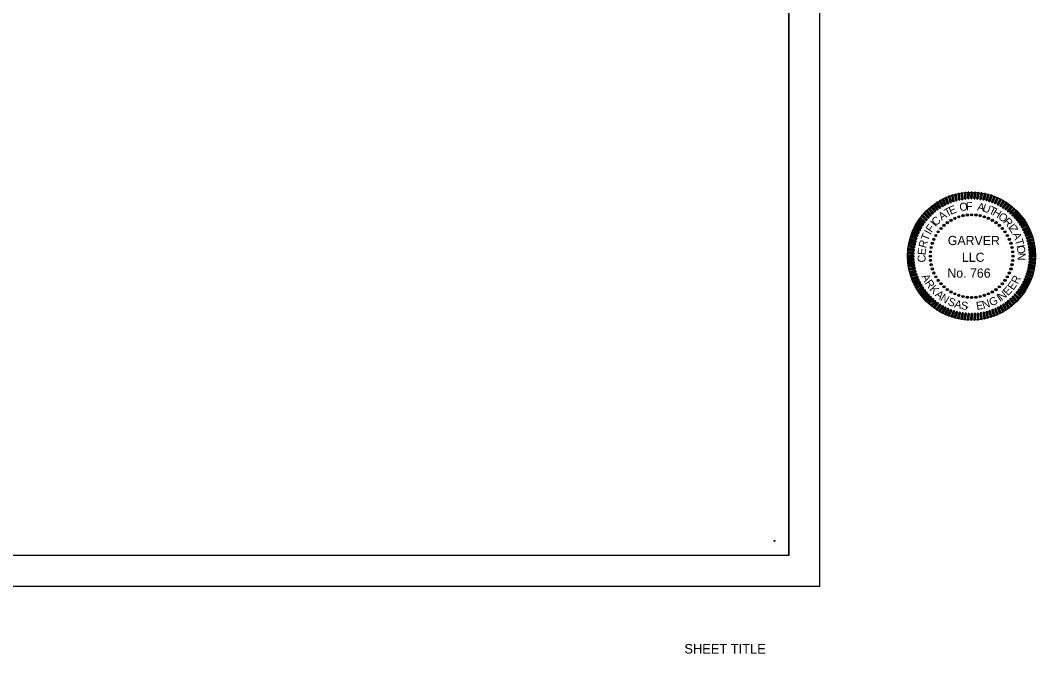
# Model space of a CAD drawing. Extents: x 0 to 38, y -1.3 to 22.5.
# Drawn here: x 19.02 to 38.05, y -1.27 to 10.6 of the extents above; entities that cross this region are included whole.
import ezdxf

# ---------------------------------------------------------------- set-up
doc = ezdxf.new("R2010")
doc.units = 0
for name, color, linetype in [('G-ANNO-STMP', 7, 'Continuous'), ('G-ANNO-TEXT', 7, 'Continuous'), ('G-Border-Paper', 7, 'Continuous'), ('G-Border-Sheet', 7, 'Continuous'), ('G-No Plot-Anchor', 7, 'Continuous'), ('G-No Plot-Border-1', 7, 'Continuous'), ('G-No Plot-Border-2', 7, 'Continuous'), ('G-No Plot-Stamp-1', 7, 'Continuous'), ('G-No Plot-Stamp-2', 7, 'Continuous')]:
    doc.layers.add(name, color=color, linetype=linetype)

# ---------------------------------------------------------------- blocks, each defined once
blk = doc.blocks.new('SEALDO')
at = {"layer": 'G-ANNO-TEXT'}
for radius in [0.0396, 0.0305, 0.0213, 0.0122, 0.00305]:
    blk.add_circle((1.403, -0.456), radius, dxfattribs=at)
blk = doc.blocks.new('SEALRI')
at = {"layer": 'G-ANNO-TEXT'}
for p, q in [((-0.023, 2.258), (-0.038, 2.081)), ((-0.008, 2.281), (-0.028, 2.056)), ((0.004, 2.286), (-0.016, 2.049)), ((0.016, 2.285), (-0.004, 2.048)), ((0.028, 2.278), (0.008, 2.052)), ((0.023, 2.076), (0.038, 2.253))]:
    blk.add_line(p, q, dxfattribs=at)
for centre, start, end in [((0.008, 2.256), 355, 175), ((-0.008, 2.078), 175, 355)]:
    blk.add_arc(centre, 0.0305, start, end, dxfattribs=at)

msp = doc.modelspace()

# ---------------------------------------------------------------- linework, layer by layer
at = {"layer": 'G-Border-Paper'}
msp.add_lwpolyline([(34, 22), (0, 22), (0, 0), (34, 0)], close=True, dxfattribs=at)
at = {"layer": 'G-Border-Sheet'}
for q in [(33.423, 21.423), (1.516, 0.577)]:
    msp.add_line((33.423, 0.577), q, dxfattribs=at)
at = {"layer": 'G-No Plot-Anchor'}
msp.add_circle((33.153, 0.847), 0.01, dxfattribs=at)
at = {"layer": 'G-No Plot-Border-1'}
msp.add_lwpolyline([(1.516, 0.577), (1.516, 21.423), (25.476, 21.423), (25.476, 20.432), (29.441, 20.432), (29.441, 20.122), (30.873, 20.122), (30.873, 17.172), (33.423, 17.172), (33.423, 0.577)], close=True, dxfattribs=at)
at = {"layer": 'G-No Plot-Border-2'}
msp.add_lwpolyline([(1.516, 0.577), (1.516, 21.423), (22.776, 21.423), (22.776, 18.473), (25.476, 18.473), (25.476, 20.432), (29.441, 20.432), (29.441, 20.122), (33.423, 20.122), (33.423, 0.577)], close=True, dxfattribs=at)
at = {"layer": 'G-No Plot-Stamp-1'}
msp.add_circle((36.844, 6.185), 1.2, dxfattribs=at)
at = {"layer": 'G-No Plot-Stamp-2'}
msp.add_circle((36.844, 6.185), 1.2, dxfattribs=at)

# ---------------------------------------------------------------- block references
at = {"layer": 'G-ANNO-STMP'}
for name, xscale, yscale, rotation in [('SEALRI', 0.524924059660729, 0.524924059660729, 30.00000000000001), ('SEALRI', 0.5249240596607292, 0.5249240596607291, 26.99999999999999), ('SEALRI', 0.5249240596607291, 0.5249240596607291, 23.99999999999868), ('SEALRI', 0.5249240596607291, 0.5249240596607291, 20.999999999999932), ('SEALRI', 0.524924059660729, 0.5249240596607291, 18), ('SEALRI', 0.524924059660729, 0.5249240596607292, 15.000000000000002), ('SEALRI', 0.524924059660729, 0.524924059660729, 12.000000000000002), ('SEALRI', 0.524924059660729, 0.524924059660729, 9), ('SEALRI', 0.5249240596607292, 0.5249240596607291, 6), ('SEALRI', 0.5249240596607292, 0.524924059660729, 3.0000000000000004), ('SEALRI', 0.5249240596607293, 0.5249240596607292, -2.9999999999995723), ('SEALRI', 0.524924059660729, 0.524924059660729, -5.9999999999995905), ('SEALRI', 0.5249240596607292, 0.5249240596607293, -8.999999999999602), ('SEALRI', 0.524924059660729, 0.5249240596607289, -11.999999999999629), ('SEALRI', 0.524924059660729, 0.524924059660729, -14.999999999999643), ('SEALRI', 0.5249240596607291, 0.524924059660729, -17.99999999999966), ('SEALRI', 0.524924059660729, 0.5249240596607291, -20.999999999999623), ('SEALRI', 0.524924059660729, 0.5249240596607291, -23.999999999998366), ('SEALRI', 0.5249240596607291, 0.5249240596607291, -26.999999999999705), ('SEALRI', 0.5249240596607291, 0.524924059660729, -29.99999999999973), ('SEALRI', 0.5249240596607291, 0.524924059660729, 44.999999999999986), ('SEALRI', 0.5249240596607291, 0.5249240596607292, 41.999999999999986), ('SEALRI', 0.5249240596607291, 0.5249240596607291, 38.999999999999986), ('SEALRI', 0.524924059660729, 0.524924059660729, 36), ('SEALRI', 0.524924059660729, 0.5249240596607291, 33), ('SEALRI', 0.5249240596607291, 0.524924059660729, -32.999999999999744), ('SEALRI', 0.524924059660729, 0.524924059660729, -35.999999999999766), ('SEALRI', 0.5249240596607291, 0.524924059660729, -38.999999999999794), ('SEALRI', 0.5249240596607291, 0.524924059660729, -41.99999999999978), ('SEALRI', 0.5249240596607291, 0.5249240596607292, -44.999999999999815), ('SEALRI', 0.5249240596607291, 0.524924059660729, 56.99999999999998), ('SEALRI', 0.524924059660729, 0.524924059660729, 54), ('SEALRI', 0.5249240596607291, 0.5249240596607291, 50.99999999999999), ('SEALRI', 0.5249240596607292, 0.5249240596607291, 47.99999999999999), ('SEALDO', 0.5249240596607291, 0.5249240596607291, 138), ('SEALDO', 0.524924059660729, 0.5249240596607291, 131.99999999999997), ('SEALDO', 0.5249240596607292, 0.5249240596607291, 125.99999999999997), ('SEALDO', 0.524924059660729, 0.5249240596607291, 119.99999999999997), ('SEALDO', 0.524924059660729, 0.5249240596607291, 113.99999999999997), ('SEALDO', 0.5249240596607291, 0.5249240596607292, 107.99999999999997), ('SEALDO', 0.5249240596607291, 0.5249240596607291, 101.99999999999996), ('SEALDO', 0.5249240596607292, 0.524924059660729, 95.99999999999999), ('SEALDO', 0.5249240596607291, 0.5249240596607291, 90), ('SEALDO', 0.5249240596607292, 0.5249240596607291, 83.99999999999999), ('SEALDO', 0.524924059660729, 0.5249240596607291, 77.99999999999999), ('SEALRI', 0.5249240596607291, 0.5249240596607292, -47.99999999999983), ('SEALRI', 0.524924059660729, 0.5249240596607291, -50.999999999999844), ('SEALRI', 0.524924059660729, 0.5249240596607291, -53.99999999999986), ('SEALRI', 0.5249240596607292, 0.5249240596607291, -56.999999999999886), ('SEALRI', 0.5249240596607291, 0.5249240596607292, 65.99999999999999), ('SEALRI', 0.5249240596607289, 0.524924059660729, 63), ('SEALRI', 0.524924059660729, 0.524924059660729, 59.999999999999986), ('SEALDO', 0.524924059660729, 0.5249240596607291, 162.00000000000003), ('SEALDO', 0.5249240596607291, 0.5249240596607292, 156.00000000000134), ('SEALDO', 0.5249240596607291, 0.524924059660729, 150), ('SEALDO', 0.524924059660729, 0.5249240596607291, 144), ('SEALDO', 0.524924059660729, 0.5249240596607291, 72), ('SEALDO', 0.5249240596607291, 0.5249240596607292, 66.00000000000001), ('SEALDO', 0.5249240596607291, 0.524924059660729, 60.00000000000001), ('SEALDO', 0.524924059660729, 0.524924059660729, 54), ('SEALRI', 0.524924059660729, 0.5249240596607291, -59.99999999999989), ('SEALRI', 0.5249240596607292, 0.5249240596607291, -62.99999999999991), ('SEALRI', 0.5249240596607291, 0.5249240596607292, -65.99999999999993), ('SEALRI', 0.524924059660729, 0.5249240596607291, 75.00000000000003), ('SEALRI', 0.524924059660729, 0.5249240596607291, 72), ('SEALRI', 0.5249240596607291, 0.5249240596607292, 68.99999999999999), ('SEALDO', 0.5249240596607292, 0.524924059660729, 174.00000000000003), ('SEALDO', 0.5249240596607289, 0.524924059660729, 168.00000000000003), ('SEALDO', 0.5249240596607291, 0.5249240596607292, 48.00000000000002), ('SEALDO', 0.5249240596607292, 0.5249240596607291, 42.000000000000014), ('SEALRI', 0.5249240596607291, 0.5249240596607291, -68.99999999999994), ('SEALRI', 0.5249240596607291, 0.5249240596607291, -71.99999999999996), ('SEALRI', 0.5249240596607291, 0.5249240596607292, -74.99999999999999), ('SEALRI', 0.5249240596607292, 0.5249240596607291, 84.00000000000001), ('SEALRI', 0.524924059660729, 0.524924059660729, 81), ('SEALRI', 0.524924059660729, 0.524924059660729, 78.00000000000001), ('SEALDO', 0.524924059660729, 0.5249240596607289, -167.99999999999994), ('SEALDO', 0.5249240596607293, 0.5249240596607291, -173.99999999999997), ('SEALDO', 0.5249240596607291, 0.5249240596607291, -179.99999999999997), ('SEALDO', 0.524924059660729, 0.524924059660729, 36), ('SEALDO', 0.5249240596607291, 0.524924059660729, 29.999999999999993), ('SEALDO', 0.5249240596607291, 0.5249240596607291, 23.99999999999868), ('SEALRI', 0.524924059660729, 0.524924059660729, -78), ('SEALRI', 0.524924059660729, 0.524924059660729, -81.00000000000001), ('SEALRI', 0.5249240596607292, 0.524924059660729, -84.00000000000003), ('SEALRI', 0.5249240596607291, 0.5249240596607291, 90.00000000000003), ('SEALRI', 0.5249240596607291, 0.5249240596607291, 87.00000000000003), ('SEALRI', 0.5249240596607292, 0.524924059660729, 93), ('SEALRI', 0.5249240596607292, 0.5249240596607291, 96.00000000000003), ('SEALDO', 0.524924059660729, 0.5249240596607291, -161.99999999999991), ('SEALDO', 0.524924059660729, 0.5249240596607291, -156.00000000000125), ('SEALDO', 0.524924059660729, 0.524924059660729, 12.000000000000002), ('SEALDO', 0.524924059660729, 0.5249240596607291, 18), ('SEALRI', 0.5249240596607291, 0.524924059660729, -96.0000000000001), ('SEALRI', 0.5249240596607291, 0.5249240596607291, -87.00000000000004), ('SEALRI', 0.5249240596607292, 0.5249240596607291, -93.00000000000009), ('SEALRI', 0.5249240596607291, 0.5249240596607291, -90.00000000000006), ('SEALRI', 0.5249240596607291, 0.5249240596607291, 99.00000000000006), ('SEALRI', 0.524924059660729, 0.5249240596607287, 102.00000000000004), ('SEALRI', 0.5249240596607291, 0.5249240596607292, 105.00000000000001), ('SEALDO', 0.5249240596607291, 0.5249240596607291, -149.99999999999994), ('SEALDO', 0.5249240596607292, 0.5249240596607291, -143.99999999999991), ('SEALDO', 0.5249240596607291, 0.5249240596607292, -137.9999999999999), ('SEALDO', 0.5249240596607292, 0.5249240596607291, 6), ('SEALRI', 0.5249240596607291, 0.524924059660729, -105.00000000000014), ('SEALRI', 0.524924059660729, 0.524924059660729, -102.00000000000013), ('SEALRI', 0.5249240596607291, 0.524924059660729, -99.00000000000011), ('SEALRI', 0.5249240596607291, 0.5249240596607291, 108.00000000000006), ('SEALRI', 0.524924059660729, 0.524924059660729, 111.00000000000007), ('SEALRI', 0.5249240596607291, 0.5249240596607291, 114.00000000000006), ('SEALRI', 0.5249240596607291, 0.5249240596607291, 117.00000000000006), ('SEALDO', 0.5249240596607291, 0.5249240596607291, -131.99999999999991), ('SEALDO', 0.5249240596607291, 0.5249240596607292, -125.9999999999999), ('SEALDO', 0.524924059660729, 0.5249240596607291, -18.000000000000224), ('SEALDO', 0.524924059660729, 0.5249240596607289, -12.000000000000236), ('SEALDO', 0.5249240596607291, 0.524924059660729, -6.000000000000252), ('SEALRI', 0.5249240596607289, 0.524924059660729, -117.00000000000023), ('SEALRI', 0.5249240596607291, 0.5249240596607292, -114.0000000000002), ('SEALRI', 0.5249240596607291, 0.5249240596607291, -111.00000000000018), ('SEALRI', 0.5249240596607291, 0.524924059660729, -108.00000000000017), ('SEALRI', 0.524924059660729, 0.524924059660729, 120.00000000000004), ('SEALRI', 0.524924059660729, 0.524924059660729, 123.00000000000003), ('SEALRI', 0.5249240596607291, 0.5249240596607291, 126.00000000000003), ('SEALRI', 0.5249240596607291, 0.5249240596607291, 129.00000000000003), ('SEALDO', 0.524924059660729, 0.5249240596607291, -119.99999999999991), ('SEALDO', 0.5249240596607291, 0.5249240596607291, -113.99999999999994), ('SEALDO', 0.5249240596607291, 0.5249240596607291, -107.99999999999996), ('SEALDO', 0.524924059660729, 0.5249240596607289, -101.99999999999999), ('SEALDO', 0.524924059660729, 0.524924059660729, -42.00000000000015), ('SEALDO', 0.524924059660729, 0.5249240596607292, -36.00000000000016), ('SEALDO', 0.524924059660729, 0.5249240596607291, -30.00000000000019), ('SEALDO', 0.5249240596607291, 0.524924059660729, -23.999999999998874), ('SEALRI', 0.524924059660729, 0.5249240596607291, -129.00000000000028), ('SEALRI', 0.5249240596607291, 0.524924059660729, -126.00000000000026), ('SEALRI', 0.524924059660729, 0.5249240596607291, -123.00000000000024), ('SEALRI', 0.5249240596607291, 0.524924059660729, -120.00000000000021), ('SEALRI', 0.5249240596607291, 0.524924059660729, 132), ('SEALRI', 0.524924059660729, 0.5249240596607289, 135), ('SEALRI', 0.5249240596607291, 0.5249240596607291, 138), ('SEALRI', 0.524924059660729, 0.5249240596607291, 140.99999999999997), ('SEALRI', 0.524924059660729, 0.5249240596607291, 144), ('SEALDO', 0.5249240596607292, 0.5249240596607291, -96), ('SEALDO', 0.5249240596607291, 0.5249240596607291, -90.00000000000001), ('SEALDO', 0.5249240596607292, 0.524924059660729, -84.00000000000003), ('SEALDO', 0.5249240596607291, 0.5249240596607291, -78.00000000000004), ('SEALDO', 0.5249240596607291, 0.524924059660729, -72.00000000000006), ('SEALDO', 0.524924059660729, 0.5249240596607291, -66.00000000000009), ('SEALDO', 0.5249240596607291, 0.5249240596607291, -60.0000000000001), ('SEALDO', 0.5249240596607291, 0.5249240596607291, -54.000000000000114), ('SEALDO', 0.5249240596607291, 0.5249240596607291, -48.00000000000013), ('SEALRI', 0.524924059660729, 0.5249240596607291, -144.00000000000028), ('SEALRI', 0.5249240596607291, 0.524924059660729, -141.0000000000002), ('SEALRI', 0.5249240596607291, 0.524924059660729, -138.00000000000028), ('SEALRI', 0.524924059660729, 0.524924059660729, -135.00000000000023), ('SEALRI', 0.524924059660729, 0.5249240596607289, -132.00000000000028), ('SEALRI', 0.524924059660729, 0.5249240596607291, 146.99999999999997), ('SEALRI', 0.524924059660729, 0.5249240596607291, 149.99999999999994), ('SEALRI', 0.5249240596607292, 0.5249240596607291, 152.99999999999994), ('SEALRI', 0.524924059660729, 0.524924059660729, 156.00000000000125), ('SEALRI', 0.524924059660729, 0.5249240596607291, 159), ('SEALRI', 0.524924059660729, 0.524924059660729, 161.99999999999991), ('SEALRI', 0.524924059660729, 0.5249240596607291, 164.99999999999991), ('SEALRI', 0.524924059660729, 0.5249240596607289, 167.99999999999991), ('SEALRI', 0.524924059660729, 0.524924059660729, -168.0000000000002), ('SEALRI', 0.524924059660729, 0.5249240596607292, -165.0000000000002), ('SEALRI', 0.524924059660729, 0.5249240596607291, -162.00000000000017), ('SEALRI', 0.5249240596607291, 0.5249240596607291, -159.00000000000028), ('SEALRI', 0.5249240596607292, 0.5249240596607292, -156.00000000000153), ('SEALRI', 0.524924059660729, 0.5249240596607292, -153.00000000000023), ('SEALRI', 0.524924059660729, 0.5249240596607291, -150.00000000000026), ('SEALRI', 0.5249240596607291, 0.524924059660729, -147.00000000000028), ('SEALRI', 0.5249240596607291, 0.524924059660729, 170.9999999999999), ('SEALRI', 0.5249240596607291, 0.524924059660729, 173.9999999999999), ('SEALRI', 0.5249240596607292, 0.5249240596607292, 176.9999999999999), ('SEALRI', 0.5249240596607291, 0.5249240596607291, 179.99999999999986), ('SEALRI', 0.5249240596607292, 0.5249240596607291, -177.00000000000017), ('SEALRI', 0.524924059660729, 0.524924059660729, -174.00000000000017), ('SEALRI', 0.5249240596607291, 0.5249240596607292, -171.00000000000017)]:
    msp.add_blockref(name, (36.845, 6.185), dxfattribs=dict(at, xscale=xscale, yscale=yscale, rotation=rotation))
at = {"layer": 'G-ANNO-STMP', "xscale": 0.5249240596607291, "yscale": 0.5249240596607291}
for name in ['SEALRI', 'SEALDO']:
    msp.add_blockref(name, (36.845, 6.185), dxfattribs=at)

# ---------------------------------------------------------------- texts
at = {"layer": 'G-ANNO-STMP'}
for s, rotation, p in [('T', 28.2771, (36.381, 6.915)), ('E', 21.6104, (36.453, 6.957)), ('O', 8.2771, (36.627, 7.025)), ('F', 1.6104, (36.741, 7.044)), ('A', 348.2771, (36.941, 7.045)), ('U', 341.2772, (37.035, 7.03)), ('T', 334.9438, (37.153, 6.992)), ('H', 328.2771, (37.221, 6.966)), ('I', 49.7408, (36.172, 6.724)), ('C', 44.3881, (36.179, 6.74)), ('A', 34.9438, (36.286, 6.846)), ('O', 319.7874, (37.329, 6.904)), ('R', 311.9933, (37.427, 6.826)), ('I', 61.6104, (36.076, 6.574)), ('F', 54.9438, (36.094, 6.615)), ('I', 307.0081, (37.519, 6.723)), ('Z', 301.6104, (37.537, 6.705)), ('R', 74.9438, (35.99, 6.326)), ('T', 67.4314, (36.025, 6.458)), ('A', 292.9752, (37.607, 6.596)), ('T', 286.3085, (37.654, 6.487)), ('E', 83.8985, (35.979, 6.197)), ('I', 281.6104, (37.684, 6.382)), ('O', 276.4823, (37.69, 6.376)), ('C', 91.8842, (35.986, 6.069)), ('N', 268.2771, (37.709, 6.25)), ('A', 296.5747, (35.903, 5.805)), ('R', 304.6183, (35.962, 5.682)), ('E', 54.7309, (37.625, 5.534)), ('R', 63.0959, (37.709, 5.649)), ('K', 313.3805, (36.046, 5.556)), ('A', 321.2584, (36.148, 5.446)), ('N', 38.9821, (37.41, 5.34)), ('E', 46.6807, (37.526, 5.432)), ('N', 329.1099, (36.246, 5.363)), ('S', 337.6294, (36.385, 5.279)), ('A', 345.4073, (36.511, 5.226)), ('S', 352.8046, (36.638, 5.19)), ('E', 10.0695, (36.943, 5.174)), ('N', 17.8686, (37.068, 5.193)), ('G', 26.4132, (37.216, 5.239)), ('I', 32.979, (37.375, 5.322)), ('-', 0.8385, (36.729, 5.171))]:
    msp.add_text(s, height=0.15, rotation=rotation, dxfattribs=at).set_placement(p)
for s, p in [('GARVER', (36.399, 6.392)), ('LLC', (36.663, 6.078)), ('No. 766', (36.391, 5.781))]:
    msp.add_text(s, height=0.1728, dxfattribs=at).set_placement(p)
at = {"layer": 'G-ANNO-TEXT'}
msp.add_text('SHEET TITLE', height=0.18, dxfattribs=at).set_placement((31.464, -1.264))

doc.saveas('drawing.dxf')
